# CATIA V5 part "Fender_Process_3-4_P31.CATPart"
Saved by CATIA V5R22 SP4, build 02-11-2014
Part number: Fender
Bounding box of the stored display mesh (mm): x -800 to 0, y -40 to 122.298, z 0 to 580
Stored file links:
  C:\DATA\Car_ASSY\教育モデル\3_SOL\Fender_Process_3-4_P31.CATPart
  C:\DATA\Car_ASSY\教育モデル\3_SOL\Car_Fender.CATPart
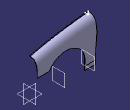
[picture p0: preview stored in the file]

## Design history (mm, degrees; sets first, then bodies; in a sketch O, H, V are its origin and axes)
Set1
  Plane1: type Offset, RefPlane yz-plane, Offset 400, reversed
  Plane2: type Offset, RefPlane Plane1, Offset 400, reversed
Body1 (main body)
Body2
  Sketch1 on yz-plane, origin (0, 0, 0), H (0, 1, 0), V (0, 0, 1)
    point P4 (100, 50)
    point P5 (10, 450)
    spline S1 through (10, 450) (100, 50)
    line L1 (0, 450) -> (10, 450)
    line L2 (0, 0) -> (0, 450)
    line L3 (100, 0) -> (0, 0)
    line L4 (100, 50) -> (100, 0)
    point P6 (100, 50)
    point P7 (10, 450)
    distance P4 L3 = 50
    distance P5 L2 = 10
    distance L4 L2 = 100
    distance L1 H = 450
    coincidence: L2 V, H L3, P4 P6, P7 P5
  Sketch2 on Plane1, origin (-400, 0, 0), H (0, 1, 0), V (0, 0, 1)
    point P4 (100, 50)
    point P5 (10, 530)
    spline S1 through (10, 530) (100, 50)
    line L1 (0, 530) -> (10, 530)
    line L2 (0, 0) -> (0, 530)
    line L3 (100, 0) -> (0, 0)
    line L4 (100, 50) -> (100, 0)
    point P6 (100, 50)
    point P7 (10, 530)
    distance P4 L3 = 50
    distance P5 L2 = 10
    distance L4 L2 = 100
    distance L1 H = 530
    coincidence: L2 V, H L3, P4 P6, P7 P5
  Sketch3 on Plane2, origin (-800, 0, 0), H (0, 1, 0), V (0, 0, 1)
    point P4 (100, 50)
    point P5 (10, 580)
    spline S1 through (10, 580) (100, 50)
    line L1 (0, 580) -> (10, 580)
    line L2 (0, 0) -> (0, 580)
    line L3 (100, 0) -> (0, 0)
    line L4 (100, 50) -> (100, 0)
    point P6 (100, 50)
    point P7 (10, 580)
    distance P4 L3 = 50
    distance P5 L2 = 10
    distance L4 L2 = 100
    distance L1 H = 580
    coincidence: L2 V, H L3, P4 P6, P7 P5
  Loft1: solid, Sections (Sketch1; Sketch2; Sketch3)
  Body3
    Sketch4 on zx-plane, origin (0, 0, 0), H (-1, 0, 0), V (0, 0, 1)
      line L1 (-46.4952, 240) -> (159.0779, 240)
      arc A1 centre (390, 110) radius 265 from (159.0779, 240) to (655, 109.9999) cw
      point P2 (390, 110)
      line L2 (655, 109.9999) -> (655, -30)
      line L3 (-46.4952, 626.6258) -> (850, 626.6258)
      line L4 (850, 626.6258) -> (850, -30)
      line L5 (850, -30) -> (655, -30)
      line L6 (-46.4952, 626.6258) -> (-46.4952, 240)
      radius A1 = 265
      distance P2 H = 110
      distance V P2 = 390
      distance H L1 = 240
      horizontal: L1 H, L3 H, L5 H
      tangency: L2 A1
      vertical: L2 V, L4 V, L6 V
    Pad1: profile Sketch4, direction (0, 1, 0), length 340, mirrored extent
  Intersect1: tool Body3
  Shell1: ExtOffset 0, Face (face of Loft1; face of Loft1; face of Pad1 from Sketch4.A1; face of Pad1 from Sketch4.L1; face of Loft1; face of Loft1), IntOffset 3
  Sketch5 on Plane2, origin (-800, 0, 0), H (0, 1, 0), V (0, 0, 1)
    line L1 (0, 580) -> (0, 545)
    line L2 (-5, 540) -> (-40, 540)
    point P2 (-40, 540)
    reference projected line E1 (10, 580) -> (0, 580)
    reference intersected line E2 (0, 0) -> (0, 580)
    arc A1 centre (-5, 545) radius 5 from (-5, 540) to (0, 545) ccw
    line L3 (-5, 537) -> (-40, 537)
    arc A2 centre (-5, 545) radius 8 from (-5, 537) to (3, 545) ccw
    line L4 (3, 580) -> (3, 545)
    line L5 (-40, 537) -> (-40, 540)
    line L6 (3, 580) -> (0, 580)
    reference projected line E3 (10, 580) -> (0, 580)
    distance E1 L2 = 40
    radius A1 = 5
    distance L1 P2 = 40
    length L5 = 3
    length L6 = 3
    radius A2 = 8
    vertical: L1 V, L4 V, L5 V
    horizontal: L2 H, L6 H, L3 H
    coincidence: L1 E2, L6 E3
    tangency: A1 L2, A1 L1, L4 A2, A2 L3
